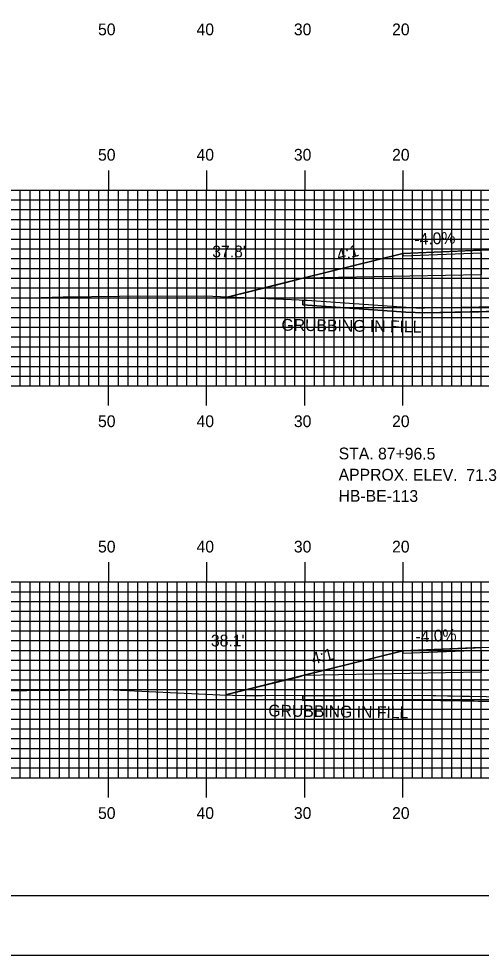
# Model space of a CAD drawing. Extents: x 1764152 to 1764495, y 442591 to 442811.
# Drawn here: x 1764258.7 to 1764305.8, y 442590.5 to 442686.2 of the extents above; entities that cross this region are included whole.
import ezdxf

# ---------------------------------------------------------------- set-up
doc = ezdxf.new("R2010")
doc.units = 0
for name, color, linetype in [('ANNOTATION', 7, 'Continuous'), ('BORDER', 7, 'Continuous'), ('BORING - NO REFUSAL', 7, 'Continuous'), ('D_Roadway_Centerline', 7, 'Continuous'), ('D_Roadway_Edge_Shoulder', 7, 'Continuous'), ('D_Roadway_SlopeLines', 7, 'Continuous'), ('D_Roadway_SubGrade', 7, 'Continuous'), ('D_Text_Standard', 7, 'Continuous'), ('GRUBBING IN FILL', 7, 'Continuous'), ('H_V ANNOTATION', 7, 'Continuous'), ('MAJOR', 7, 'Continuous'), ('MINOR', 7, 'Continuous'), ('PLOT BOUNDARY', 7, 'Continuous'), ('S_Roadway_Centerline', 7, 'Continuous')]:
    doc.layers.add(name, color=color, linetype=linetype)

msp = doc.modelspace()

# ---------------------------------------------------------------- linework, layer by layer
at = {"layer": 'BORDER'}
msp.add_lwpolyline([(1764168.232, 442596.665), (1764488.232, 442596.665), (1764488.232, 442806.665), (1764168.232, 442806.665)], close=True, dxfattribs=at)
at = {"layer": 'D_Roadway_Centerline'}
for points in [[(1764280.078, 442657.758), (1764284.623, 442658.894), (1764287.657, 442659.653), (1764292.966, 442660.981), (1764297.813, 442662.192), (1764297.832, 442662.197), (1764297.847, 442662.198), (1764304.946, 442662.482), (1764305.832, 442662.517), (1764317.826, 442662.757), (1764317.831, 442662.757), (1764329.826, 442662.517), (1764329.832, 442662.517), (1764329.836, 442662.517), (1764336.402, 442662.254), (1764337.832, 442662.197), (1764339.339, 442661.82), (1764348.006, 442659.653), (1764349.62, 442659.25), (1764349.832, 442659.197), (1764351.315, 442658.826), (1764361.371, 442656.312)], [(1764279.768, 442617.12), (1764287.379, 442619.022), (1764287.658, 442619.092), (1764296.589, 442621.326), (1764297.831, 442621.636), (1764305.196, 442621.931), (1764305.832, 442621.956), (1764317.832, 442622.196), (1764329.832, 442621.956), (1764333.031, 442621.828), (1764337.448, 442621.652), (1764337.831, 442621.636), (1764341.569, 442620.702), (1764348.004, 442619.093), (1764348.006, 442619.092), (1764349.264, 442618.778), (1764349.831, 442618.636), (1764349.833, 442618.636), (1764350.364, 442618.503), (1764362.819, 442615.389)]]:
    msp.add_lwpolyline(points, dxfattribs=at)
at = {"layer": 'D_Roadway_Edge_Shoulder'}
for points in [[(1764305.832, 442662.517), (1764297.832, 442662.197), (1764297.832, 442661.947), (1764305.832, 442662.267)], [(1764305.832, 442621.956), (1764297.831, 442621.636), (1764297.831, 442621.386), (1764305.832, 442621.706)]]:
    msp.add_lwpolyline(points, close=True, dxfattribs=at)
at = {"layer": 'D_Roadway_SlopeLines'}
for points in [[(1764297.832, 442662.197), (1764287.657, 442659.653), (1764280.078, 442657.758)], [(1764297.831, 442621.636), (1764287.658, 442619.092), (1764279.768, 442617.12)]]:
    msp.add_lwpolyline(points, dxfattribs=at)
at = {"layer": 'D_Roadway_SubGrade'}
for points in [[(1764297.832, 442661.947), (1764305.832, 442662.267), (1764305.832, 442661.85), (1764305.832, 442660.017), (1764287.657, 442659.653), (1764297.832, 442662.197)], [(1764297.831, 442621.386), (1764305.832, 442621.706), (1764305.832, 442621.289), (1764305.832, 442619.456), (1764287.658, 442619.092), (1764297.831, 442621.636)]]:
    msp.add_lwpolyline(points, close=True, dxfattribs=at)
at = {"layer": 'GRUBBING IN FILL'}
for p, q in [((1764287.657, 442657.431), (1764287.657, 442656.941)), ((1764287.658, 442617.068), (1764287.658, 442616.568))]:
    msp.add_line(p, q, dxfattribs=at)
for points in [[(1764315.517, 442657.067), (1764317.832, 442657.121), (1764317.832, 442656.621), (1764315.529, 442656.567), (1764309.549, 442656.325), (1764304.695, 442656.224), (1764300.033, 442656.141), (1764298.141, 442656.207), (1764292.899, 442656.574), (1764287.657, 442656.941), (1764287.657, 442657.431), (1764288.087, 442657.412), (1764298.173, 442656.706), (1764299.591, 442656.645), (1764304.679, 442656.723), (1764311.395, 442656.917)], [(1764315.517, 442657.067), (1764317.832, 442657.121), (1764317.832, 442656.621), (1764315.529, 442656.567), (1764309.549, 442656.325), (1764304.695, 442656.224), (1764300.033, 442656.141), (1764298.141, 442656.207), (1764292.899, 442656.574), (1764287.657, 442656.941), (1764287.657, 442657.431), (1764288.087, 442657.412), (1764298.173, 442656.706), (1764299.591, 442656.645), (1764304.679, 442656.723), (1764311.395, 442656.917)], [(1764287.658, 442616.568), (1764287.658, 442617.068), (1764291.507, 442617.073), (1764299.468, 442617.083), (1764306.366, 442616.966), (1764307.832, 442616.943), (1764308.883, 442616.927), (1764312.769, 442616.714), (1764316.654, 442616.502), (1764317.299, 442616.475), (1764317.832, 442616.542), (1764317.832, 442616.038), (1764317.32, 442615.974), (1764316.63, 442616.002), (1764312.748, 442616.215), (1764308.865, 442616.427), (1764307.832, 442616.443), (1764306.353, 442616.467), (1764303.84, 442616.506), (1764299.464, 442616.582), (1764293.561, 442616.575)], [(1764287.658, 442616.568), (1764287.658, 442617.068), (1764291.507, 442617.073), (1764299.468, 442617.083), (1764306.366, 442616.966), (1764307.832, 442616.943), (1764308.883, 442616.927), (1764312.769, 442616.714), (1764316.654, 442616.502), (1764317.299, 442616.475), (1764317.832, 442616.542), (1764317.832, 442616.038), (1764317.32, 442615.974), (1764316.63, 442616.002), (1764312.748, 442616.215), (1764308.865, 442616.427), (1764307.832, 442616.443), (1764306.353, 442616.467), (1764303.84, 442616.506), (1764299.464, 442616.582), (1764293.561, 442616.575)]]:
    msp.add_lwpolyline(points, close=True, dxfattribs=at)
for points in [[(1764287.657, 442656.941), (1764298.141, 442656.207), (1764299.135, 442656.149), (1764300.033, 442656.141), (1764309.357, 442656.306), (1764309.741, 442656.344), (1764313.105, 442656.491), (1764313.933, 442656.525), (1764315.529, 442656.567), (1764330.646, 442656.921), (1764348.005, 442656.301)], [(1764287.658, 442616.568), (1764299.464, 442616.582), (1764303.84, 442616.506), (1764308.865, 442616.427), (1764316.63, 442616.002), (1764317.32, 442615.974), (1764319.142, 442616.202), (1764322.432, 442616.084), (1764328.807, 442615.827), (1764334.932, 442615.647), (1764342.9, 442615.828), (1764348.006, 442615.595)]]:
    msp.add_lwpolyline(points, dxfattribs=at)
at = {"layer": 'MAJOR'}
for p, q in [((1764267.832, 442670.669), (1764267.832, 442668.665)), ((1764277.832, 442670.669), (1764277.832, 442668.665)), ((1764287.832, 442670.669), (1764287.832, 442668.665)), ((1764297.832, 442670.669), (1764297.832, 442668.665)), ((1764177.832, 442668.665), (1764457.832, 442668.665)), ((1764177.832, 442668.665), (1764457.832, 442668.665)), ((1764267.832, 442648.665), (1764267.832, 442668.665)), ((1764277.832, 442648.665), (1764277.832, 442668.665)), ((1764287.832, 442648.665), (1764287.832, 442668.665)), ((1764297.832, 442648.665), (1764297.832, 442668.665)), ((1764177.832, 442663.665), (1764457.832, 442663.665)), ((1764177.832, 442658.665), (1764457.832, 442658.665)), ((1764177.832, 442653.665), (1764457.832, 442653.665)), ((1764177.832, 442648.665), (1764457.832, 442648.665)), ((1764177.832, 442648.665), (1764457.832, 442648.665)), ((1764267.832, 442646.661), (1764267.832, 442648.665)), ((1764277.832, 442646.661), (1764277.832, 442648.665)), ((1764287.832, 442646.661), (1764287.832, 442648.665)), ((1764297.832, 442646.661), (1764297.832, 442648.665)), ((1764267.832, 442630.669), (1764267.832, 442628.665)), ((1764277.832, 442630.669), (1764277.832, 442628.665)), ((1764287.832, 442630.669), (1764287.832, 442628.665)), ((1764297.832, 442630.669), (1764297.832, 442628.665)), ((1764177.832, 442628.665), (1764457.832, 442628.665)), ((1764177.832, 442628.665), (1764457.832, 442628.665)), ((1764267.832, 442608.665), (1764267.832, 442628.665)), ((1764277.832, 442608.665), (1764277.832, 442628.665)), ((1764287.832, 442608.665), (1764287.832, 442628.665)), ((1764297.832, 442608.665), (1764297.832, 442628.665)), ((1764177.832, 442623.665), (1764457.832, 442623.665)), ((1764177.832, 442618.665), (1764457.832, 442618.665)), ((1764177.832, 442613.665), (1764457.832, 442613.665)), ((1764177.832, 442608.665), (1764457.832, 442608.665)), ((1764177.832, 442608.665), (1764457.832, 442608.665)), ((1764267.832, 442606.661), (1764267.832, 442608.665)), ((1764277.832, 442606.661), (1764277.832, 442608.665)), ((1764287.832, 442606.661), (1764287.832, 442608.665)), ((1764297.832, 442606.661), (1764297.832, 442608.665))]:
    msp.add_line(p, q, dxfattribs=at)
at = {"layer": 'MINOR'}
for p, q in [((1764258.832, 442648.665), (1764258.832, 442668.665)), ((1764259.832, 442648.665), (1764259.832, 442668.665)), ((1764260.832, 442648.665), (1764260.832, 442668.665)), ((1764261.832, 442648.665), (1764261.832, 442668.665)), ((1764262.832, 442648.665), (1764262.832, 442668.665)), ((1764263.832, 442648.665), (1764263.832, 442668.665)), ((1764264.832, 442648.665), (1764264.832, 442668.665)), ((1764265.832, 442648.665), (1764265.832, 442668.665)), ((1764266.832, 442648.665), (1764266.832, 442668.665)), ((1764268.832, 442648.665), (1764268.832, 442668.665)), ((1764269.832, 442648.665), (1764269.832, 442668.665)), ((1764270.832, 442648.665), (1764270.832, 442668.665)), ((1764271.832, 442648.665), (1764271.832, 442668.665)), ((1764272.832, 442648.665), (1764272.832, 442668.665)), ((1764273.832, 442648.665), (1764273.832, 442668.665)), ((1764274.832, 442648.665), (1764274.832, 442668.665)), ((1764275.832, 442648.665), (1764275.832, 442668.665)), ((1764276.832, 442648.665), (1764276.832, 442668.665)), ((1764278.832, 442648.665), (1764278.832, 442668.665)), ((1764279.832, 442648.665), (1764279.832, 442668.665)), ((1764280.832, 442648.665), (1764280.832, 442668.665)), ((1764281.832, 442648.665), (1764281.832, 442668.665)), ((1764282.832, 442648.665), (1764282.832, 442668.665)), ((1764283.832, 442648.665), (1764283.832, 442668.665)), ((1764284.832, 442648.665), (1764284.832, 442668.665)), ((1764285.832, 442648.665), (1764285.832, 442668.665)), ((1764286.832, 442648.665), (1764286.832, 442668.665)), ((1764288.832, 442648.665), (1764288.832, 442668.665)), ((1764289.832, 442648.665), (1764289.832, 442668.665)), ((1764290.832, 442648.665), (1764290.832, 442668.665)), ((1764291.832, 442648.665), (1764291.832, 442668.665)), ((1764292.832, 442648.665), (1764292.832, 442668.665)), ((1764293.832, 442648.665), (1764293.832, 442668.665)), ((1764294.832, 442648.665), (1764294.832, 442668.665)), ((1764295.832, 442648.665), (1764295.832, 442668.665)), ((1764296.832, 442648.665), (1764296.832, 442668.665)), ((1764298.832, 442648.665), (1764298.832, 442668.665)), ((1764299.832, 442648.665), (1764299.832, 442668.665)), ((1764300.832, 442648.665), (1764300.832, 442668.665)), ((1764301.832, 442648.665), (1764301.832, 442668.665)), ((1764302.832, 442648.665), (1764302.832, 442668.665)), ((1764303.832, 442648.665), (1764303.832, 442668.665)), ((1764304.832, 442648.665), (1764304.832, 442668.665)), ((1764305.832, 442648.665), (1764305.832, 442668.665)), ((1764177.832, 442667.665), (1764457.832, 442667.665)), ((1764177.832, 442666.665), (1764457.832, 442666.665)), ((1764177.832, 442665.665), (1764457.832, 442665.665)), ((1764177.832, 442664.665), (1764457.832, 442664.665)), ((1764177.832, 442662.665), (1764457.832, 442662.665)), ((1764177.832, 442661.665), (1764457.832, 442661.665)), ((1764177.832, 442660.665), (1764457.832, 442660.665)), ((1764177.832, 442659.665), (1764457.832, 442659.665)), ((1764177.832, 442657.665), (1764457.832, 442657.665)), ((1764177.832, 442656.665), (1764457.832, 442656.665)), ((1764177.832, 442655.665), (1764457.832, 442655.665)), ((1764177.832, 442654.665), (1764457.832, 442654.665)), ((1764177.832, 442652.665), (1764457.832, 442652.665)), ((1764177.832, 442651.665), (1764457.832, 442651.665)), ((1764177.832, 442650.665), (1764457.832, 442650.665)), ((1764177.832, 442649.665), (1764457.832, 442649.665)), ((1764258.832, 442608.665), (1764258.832, 442628.665)), ((1764259.832, 442608.665), (1764259.832, 442628.665)), ((1764260.832, 442608.665), (1764260.832, 442628.665)), ((1764261.832, 442608.665), (1764261.832, 442628.665)), ((1764262.832, 442608.665), (1764262.832, 442628.665)), ((1764263.832, 442608.665), (1764263.832, 442628.665)), ((1764264.832, 442608.665), (1764264.832, 442628.665)), ((1764265.832, 442608.665), (1764265.832, 442628.665)), ((1764266.832, 442608.665), (1764266.832, 442628.665)), ((1764268.832, 442608.665), (1764268.832, 442628.665)), ((1764269.832, 442608.665), (1764269.832, 442628.665)), ((1764270.832, 442608.665), (1764270.832, 442628.665)), ((1764271.832, 442608.665), (1764271.832, 442628.665)), ((1764272.832, 442608.665), (1764272.832, 442628.665)), ((1764273.832, 442608.665), (1764273.832, 442628.665)), ((1764274.832, 442608.665), (1764274.832, 442628.665)), ((1764275.832, 442608.665), (1764275.832, 442628.665)), ((1764276.832, 442608.665), (1764276.832, 442628.665)), ((1764278.832, 442608.665), (1764278.832, 442628.665)), ((1764279.832, 442608.665), (1764279.832, 442628.665)), ((1764280.832, 442608.665), (1764280.832, 442628.665)), ((1764281.832, 442608.665), (1764281.832, 442628.665)), ((1764282.832, 442608.665), (1764282.832, 442628.665)), ((1764283.832, 442608.665), (1764283.832, 442628.665)), ((1764284.832, 442608.665), (1764284.832, 442628.665)), ((1764285.832, 442608.665), (1764285.832, 442628.665)), ((1764286.832, 442608.665), (1764286.832, 442628.665)), ((1764288.832, 442608.665), (1764288.832, 442628.665)), ((1764289.832, 442608.665), (1764289.832, 442628.665)), ((1764290.832, 442608.665), (1764290.832, 442628.665)), ((1764291.832, 442608.665), (1764291.832, 442628.665)), ((1764292.832, 442608.665), (1764292.832, 442628.665)), ((1764293.832, 442608.665), (1764293.832, 442628.665)), ((1764294.832, 442608.665), (1764294.832, 442628.665)), ((1764295.832, 442608.665), (1764295.832, 442628.665)), ((1764296.832, 442608.665), (1764296.832, 442628.665)), ((1764298.832, 442608.665), (1764298.832, 442628.665)), ((1764299.832, 442608.665), (1764299.832, 442628.665)), ((1764300.832, 442608.665), (1764300.832, 442628.665)), ((1764301.832, 442608.665), (1764301.832, 442628.665)), ((1764302.832, 442608.665), (1764302.832, 442628.665)), ((1764303.832, 442608.665), (1764303.832, 442628.665)), ((1764304.832, 442608.665), (1764304.832, 442628.665)), ((1764305.832, 442608.665), (1764305.832, 442628.665)), ((1764177.832, 442627.665), (1764457.832, 442627.665)), ((1764177.832, 442626.665), (1764457.832, 442626.665)), ((1764177.832, 442625.665), (1764457.832, 442625.665)), ((1764177.832, 442624.665), (1764457.832, 442624.665)), ((1764177.832, 442622.665), (1764457.832, 442622.665)), ((1764177.832, 442621.665), (1764457.832, 442621.665)), ((1764177.832, 442620.665), (1764457.832, 442620.665)), ((1764177.832, 442619.665), (1764457.832, 442619.665)), ((1764177.832, 442617.665), (1764457.832, 442617.665)), ((1764177.832, 442616.665), (1764457.832, 442616.665)), ((1764177.832, 442615.665), (1764457.832, 442615.665)), ((1764177.832, 442614.665), (1764457.832, 442614.665)), ((1764177.832, 442612.665), (1764457.832, 442612.665)), ((1764177.832, 442611.665), (1764457.832, 442611.665)), ((1764177.832, 442610.665), (1764457.832, 442610.665)), ((1764177.832, 442609.665), (1764457.832, 442609.665))]:
    msp.add_line(p, q, dxfattribs=at)
at = {"layer": 'PLOT BOUNDARY'}
msp.add_lwpolyline([(1764152.045, 442590.547), (1764492.045, 442590.547), (1764492.045, 442810.547), (1764152.045, 442810.547)], close=True, dxfattribs=at)
at = {"layer": 'S_Roadway_Centerline'}
for points in [[(1764251.278, 442657.549), (1764259.854, 442657.646), (1764263.196, 442657.753), (1764268.944, 442657.824), (1764277.66, 442657.863), (1764288.087, 442657.412), (1764298.173, 442656.706), (1764299.151, 442656.648), (1764300.031, 442656.641), (1764309.327, 442656.806), (1764309.705, 442656.843), (1764313.084, 442656.991), (1764313.916, 442657.025), (1764315.517, 442657.067), (1764330.649, 442657.421), (1764347.696, 442656.812), (1764348.703, 442656.8), (1764349.029, 442656.775), (1764358.973, 442656.27), (1764362.202, 442656.327), (1764366.149, 442656.697)], [(1764251.625, 442617.494), (1764263.457, 442617.607), (1764267.585, 442617.666), (1764279.171, 442617.138), (1764281.746, 442617.058), (1764283.546, 442617.063), (1764299.468, 442617.083), (1764303.849, 442617.006), (1764308.883, 442616.927), (1764316.654, 442616.502), (1764317.299, 442616.475), (1764319.12, 442616.703), (1764322.451, 442616.583), (1764328.825, 442616.326), (1764334.934, 442616.148), (1764342.905, 442616.329), (1764361.604, 442615.473), (1764363.987, 442615.308), (1764366.022, 442615.67)]]:
    msp.add_lwpolyline(points, dxfattribs=at)

# ---------------------------------------------------------------- texts
at = {"layer": 'ANNOTATION'}
for s, rotation, p in [('-4.0%', 2.29056, (1764299.028, 442663.047)), ('4:1', 14.0382, (1764291.27, 442661.418)), ('-4.0%', 2.29053, (1764299.145, 442622.49)), ('4:1', 14.03946, (1764288.68, 442620.216))]:
    msp.add_text(s, height=1.2, rotation=rotation, dxfattribs=at).set_placement(p)
at = {"layer": 'BORING - NO REFUSAL'}
for s, p in [('STA. 87+96.5', (1764291.295, 442641.175)), ('APPROX. ELEV.  71.3', (1764291.288, 442639.015)), ('HB-BE-113', (1764291.281, 442636.855))]:
    msp.add_text(s, height=1.2, rotation=359.81416, dxfattribs=at).set_placement(p)
at = {"layer": 'D_Text_Standard'}
for s, p in [("37.8'", (1764278.405, 442661.793)), ("38.1'", (1764278.27, 442622.074))]:
    msp.add_text(s, height=1.2, dxfattribs=at).set_placement(p)
at = {"layer": 'GRUBBING IN FILL'}
for p in [(1764285.46, 442654.312), (1764284.12, 442614.935)]:
    msp.add_text('GRUBBING IN FILL', height=1.2, rotation=359.19507, dxfattribs=at).set_placement(p)
at = {"layer": 'H_V ANNOTATION'}
for s, p in [('50', (1764266.761, 442684.465)), ('40', (1764276.804, 442684.465)), ('30', (1764286.729, 442684.465)), ('20', (1764296.74, 442684.465)), ('50', (1764266.761, 442671.665)), ('40', (1764276.804, 442671.665)), ('30', (1764286.729, 442671.665)), ('20', (1764296.74, 442671.665)), ('50', (1764266.761, 442644.465)), ('40', (1764276.804, 442644.465)), ('30', (1764286.729, 442644.465)), ('20', (1764296.74, 442644.465)), ('50', (1764266.761, 442631.665)), ('40', (1764276.804, 442631.665)), ('30', (1764286.729, 442631.665)), ('20', (1764296.74, 442631.665)), ('50', (1764266.761, 442604.465)), ('40', (1764276.804, 442604.465)), ('30', (1764286.729, 442604.465)), ('20', (1764296.74, 442604.465))]:
    msp.add_text(s, height=1.2, dxfattribs=at).set_placement(p)

doc.saveas('drawing.dxf')
